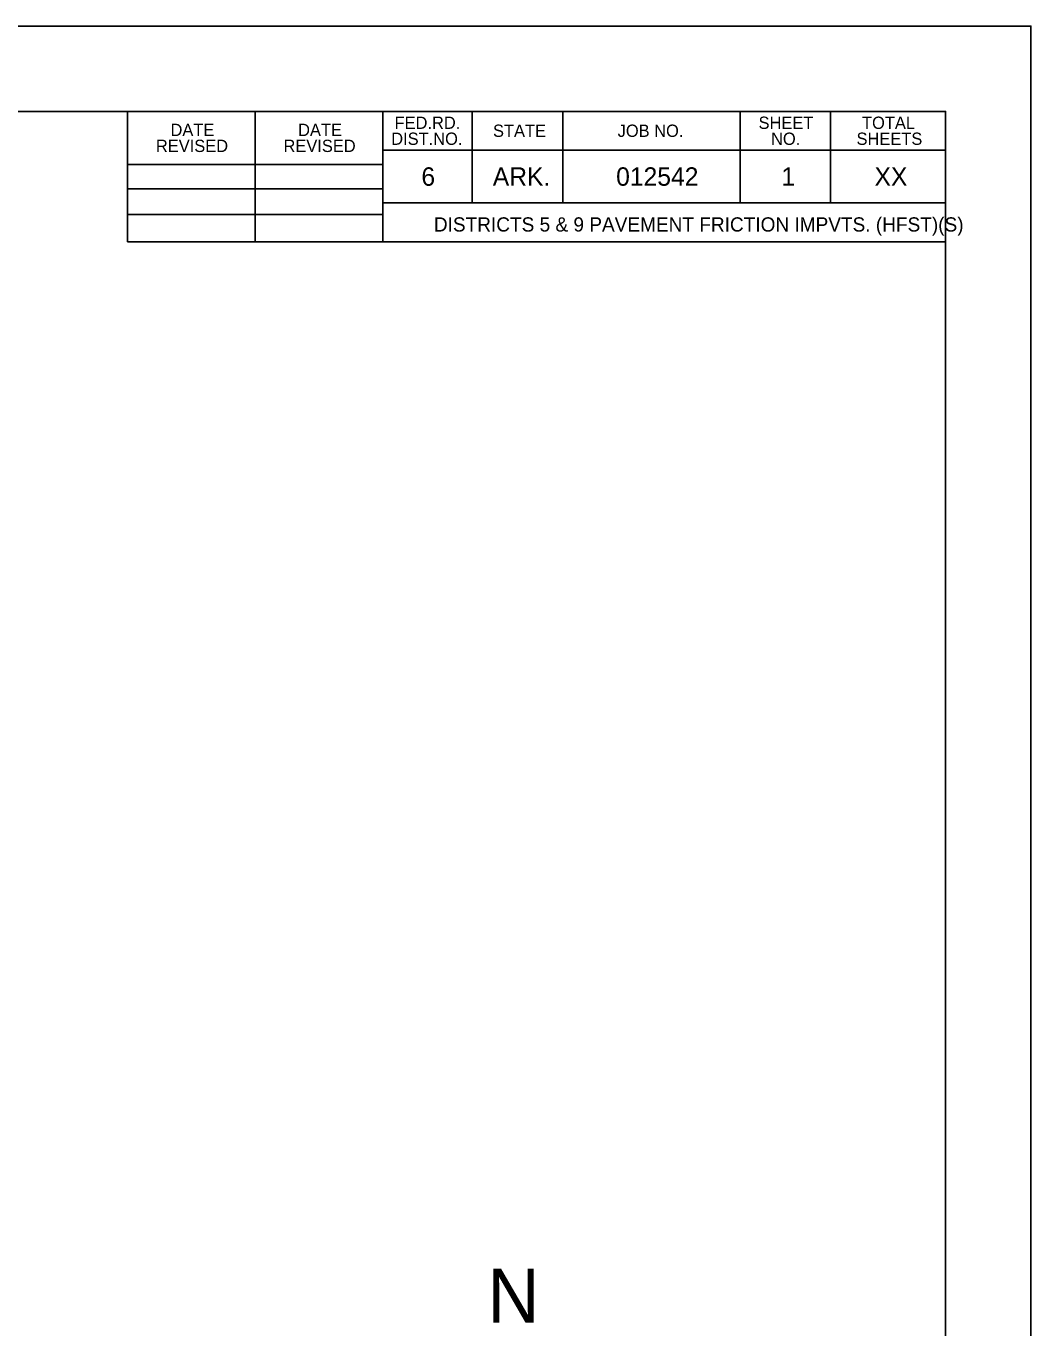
# Model space of a CAD drawing. Extents: x -819161 to 80911, y -6604 to 768454.
# Drawn here: x 29472 to 32416, y 4489 to 8305 of the extents above; entities that cross this region are included whole.
import ezdxf

# ---------------------------------------------------------------- set-up
doc = ezdxf.new("R2010")
doc.units = 0
for name, color, linetype in [('DSN_DRFT_Junk-No-Plot', 7, 'Continuous'), ('R_Draft', 7, 'Continuous'), ('SHET_Annotations', 7, 'Continuous'), ('SHET_Border-Lines', 7, 'Continuous'), ('SHET_Border-Text', 7, 'Continuous'), ('SHET_Stamp-Prelim', 7, 'Continuous')]:
    doc.layers.add(name, color=color, linetype=linetype)

msp = doc.modelspace()

# ---------------------------------------------------------------- linework, layer by layer
at = {"layer": 'DSN_DRFT_Junk-No-Plot'}
msp.add_lwpolyline([(21415.7, -195.5), (32415.7, -195.5), (32415.7, 8304.5), (21415.7, 8304.5)], close=True, dxfattribs=at)
at = {"layer": 'SHET_Border-Lines'}
for p, q in [((29769.8, 7672.5), (29769.8, 8054.5)), ((30143.5, 7672.5), (30143.5, 8054.5)), ((30517.2, 8054.5), (30517.2, 7672.5)), ((30778.8, 8054.5), (30778.8, 7786.2)), ((31044.3, 8054.5), (31044.3, 7786.2)), ((31563.7, 8054.5), (31563.7, 7786.2)), ((31829.1, 8054.5), (31829.1, 7786.2)), ((32165.7, 7940.9), (30517.2, 7940.9)), ((29769.8, 7899.1), (30517.2, 7899.1)), ((29769.8, 7827.2), (30517.2, 7827.2)), ((32165.7, 7786.2), (30517.2, 7786.2)), ((30630.4, 7786.2), (32165.7, 7786.2)), ((29769.8, 7752.1), (30517.2, 7752.1)), ((32165.7, 7672.5), (29769.8, 7672.5))]:
    msp.add_line(p, q, dxfattribs=at)
msp.add_lwpolyline([(21665.7, 8054.5), (32165.7, 8054.5), (32165.7, 54.5), (21665.7, 54.5)], close=True, dxfattribs=at)
at = {"layer": 'SHET_Stamp-Prelim'}
msp.add_lwpolyline([(31340.8, 7672.2), (31342.1, 7672.2), (31342.1, 7672.5), (31340.8, 7672.5)], close=True, dxfattribs=at)

# ---------------------------------------------------------------- texts
at = {"layer": 'R_Draft'}
msp.add_text('N', height=158.1, dxfattribs=at).set_placement((30823.6, 4504.8))
at = {"layer": 'SHET_Annotations'}
for s, height, p in [('6', 54, (30630.4, 7836.5)), ('ARK.', 54, (30839.5, 7836.5)), ('012542', 54, (31200.8, 7836.5)), ('1', 54, (31684.7, 7836.5)), ('XX', 54, (31957.5, 7836.5)), ('DISTRICTS 5 & 9 PAVEMENT FRICTION IMPVTS. (HFST)(S)', 41.683, (30666.9, 7702.3))]:
    msp.add_text(s, height=height, dxfattribs=at).set_placement(p)
at = {"layer": 'SHET_Border-Text'}
for s, p in [('DATE', (29895.5, 7982.2)), ('DATE', (30269.2, 7982.2)), ('FED.RD.', (30551.8, 8003.1)), ('STATE', (30840.1, 7979.7)), ('JOB NO.', (31205.2, 7979.7)), ('SHEET', (31617.9, 8003.1)), ('TOTAL', (31921, 8003.1)), ('DIST.NO.', (30542, 7956.3)), ('NO.', (31654.5, 7956.3)), ('SHEETS', (31904.9, 7956.3)), ('REVISED', (29852.8, 7935.4)), ('REVISED', (30226.5, 7935.4))]:
    msp.add_text(s, height=36, dxfattribs=at).set_placement(p)
at = {"layer": 'SHET_Stamp-Prelim'}
for s, height, p in [('PRELIMINARY', 0.0975, (31340.9, 7672.3)), ('SUBJECT TO REVISION', 0.0675, (31341, 7672.2))]:
    msp.add_text(s, height=height, dxfattribs=at).set_placement(p)

doc.saveas('drawing.dxf')
